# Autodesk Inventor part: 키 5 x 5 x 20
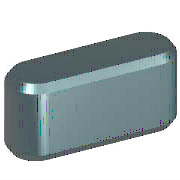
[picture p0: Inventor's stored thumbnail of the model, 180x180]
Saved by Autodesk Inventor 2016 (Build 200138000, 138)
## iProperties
IsCustomPart: 1
Created: 2012-02
Part Number: 키 5 x 5 x 20
Material: 강철, 연강
Description: 키 및 해당 키홈
Document SubType Name: Modeling
Standard: KS B 1311
Designer: mduedu
Standards Organization: KS
Language: ko-KR
Size Designation: 5 x 5 x 20
Categories: <MemberInstance><Categories><Category DisplayName="샤프트 부품" InternalName="7f7aeb1f-a693-4053-b835-cee3144e0d98" Mnemonic="SHFT"><Category DisplayName="키" Interna
Density: 1 g/cm^3
Appearance: 노란색
Author: mduedu
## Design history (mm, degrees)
workplane "Work Plane1"
workplane "Work Plane2"
sketch "스케치1"
  geometry: L1 (2.5, 2.5)-(17.5, 2.5); L2 (17.5, -2.5)-(2.5, -2.5); L3 (0, 9.4)-(0, -7.4) reference; L4 (-5, 0)-(30, 0) reference; L5 (20, 0)-(20, 7); A1 r 2.5 centre (2.5, 0) between (2.5, 2.5) and (2.5, -2.5); A2 r 2.5 centre (17.5, 0) between (17.5, -2.5) and (17.5, 2.5)
  constraints: 6 end point, 5 point on circle, 4 tangent, 3 point on line, 2 centre point, 1 horizontal, 1 parallel, 1 perpendicular
  dimensions: "d0" = 2.5 radius of A1 (= 0.5 x PB); "d13" = 2.5 radius of A2 (= 0.5 x PB); "d14" = 20 distance between parallel lines of L5 L3 (= NLG)
extrude "본체1" new body sketch "스케치1" taper "d3" = 0 deg; stored distance "d4" = 10
workplane "Work Plane3"
body "Solid1"
chamfer "모따기1" distance "d8" = 0.4 (= PHH); stored, may be unused: second distance "d9" = 0.4 (= PHH), angle "d15" = 45 deg
other parameters: "d1" = -3 (= -PNT), "d2" = 2 (= PH - PNT), "NLG" = 20 [user parameter; used in 3 equation terms], "PB" = 5 [user parameter; used in 2 equation terms], "PNT" = 3 [user parameter; used in 2 equation terms], "PH" = 5 [user parameter; used in 1 equation term], "PHH" = 0.4 [user parameter; used in 2 equation terms], "d10" = 0, "d16" = 0, "d17" = 0, "d18" = 0, "WDMIN" = 12 [user parameter], "WDMAX" = 17 [user parameter], "RR" = 0.16 [user parameter], "PUEB" = 2.3 [user parameter]
